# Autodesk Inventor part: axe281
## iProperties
Shininess: 21.0
Length Units: 11269
Angle Units: 11279
Time Units: 11290
Mass Units: 11283
Length Display Precision: 3
Angle Display Precision: 2
Compacted: True
Created: 2001-12
Part Number: axe281
Material: Par défaut
Document SubType Name: Modélisation
Designer: pichon
Density: 0.0
Volumn: 0.0
Area: 0.0
PropertySet Name: Model Information
Control State: 0
Master: False
Checked Out: False
Author: pichon
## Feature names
1. Extrusion1
2. Extrusion2
3. Chanfrein1 [Chamfer]
4. Extrusion3
